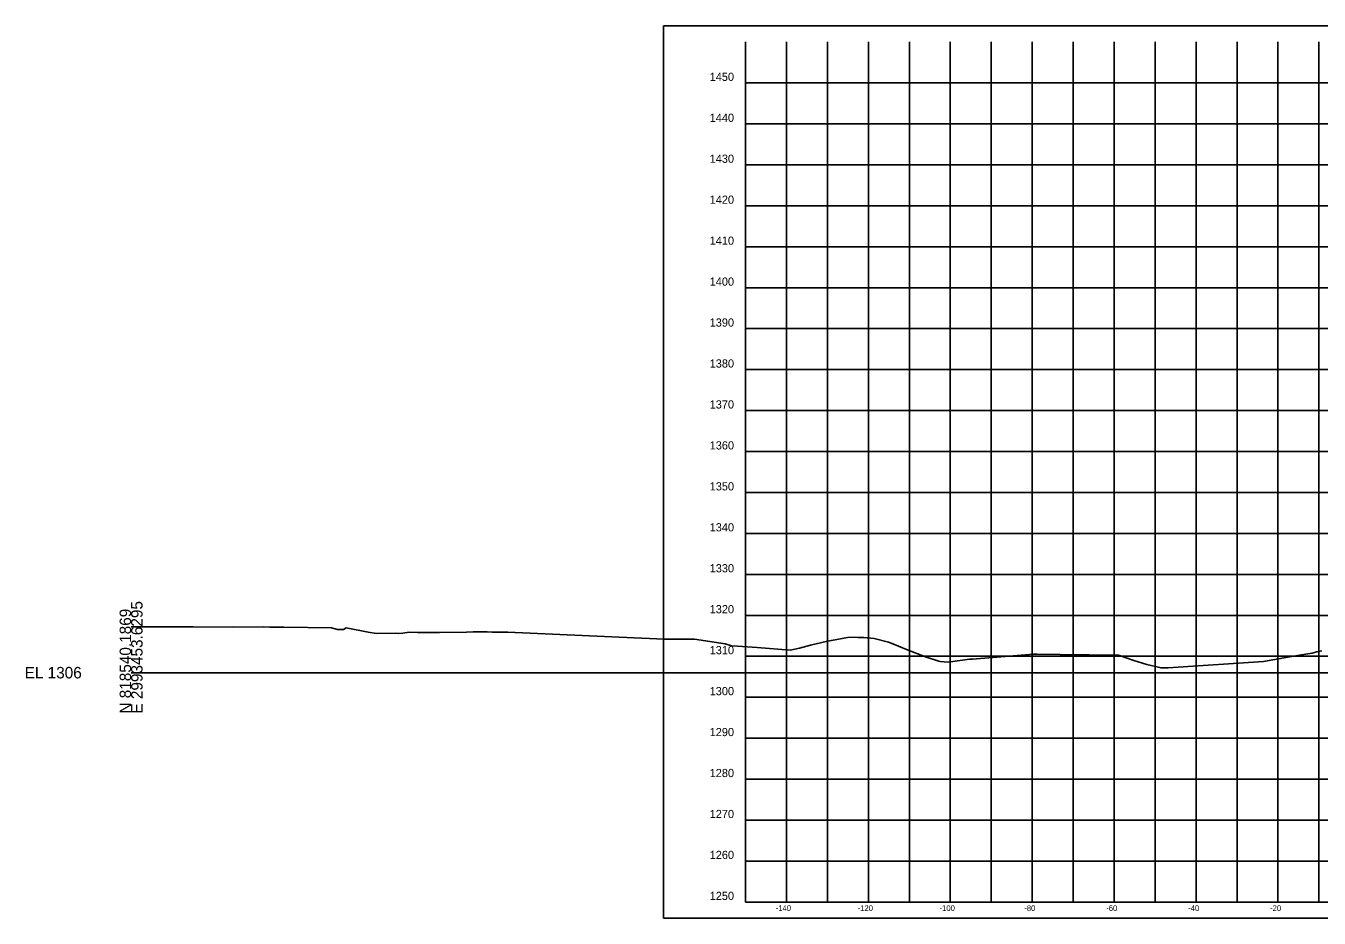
# Model space of a CAD drawing. Extents: x -26 to 603, y -60 to 663.
# Drawn here: x -25.7 to 290, y -59.9 to 157.9 of the extents above; entities that cross this region are included whole.
import ezdxf

# ---------------------------------------------------------------- set-up
doc = ezdxf.new("R2010")
doc.units = 0
for name, color, linetype in [('DESIGN - SHEET - Corner Text', 7, 'Continuous'), ('DESIGN - SHEET - Light Grid', 7, 'Continuous'), ('DESIGN - SHEET - Linework', 7, 'Continuous'), ('DESIGN - SHEET - Plot Shape', 7, 'Continuous'), ('SURVEY - GROUND - Top of Ground', 7, 'Continuous')]:
    doc.layers.add(name, color=color, linetype=linetype)

msp = doc.modelspace()

# ---------------------------------------------------------------- linework, layer by layer
at = {"layer": 'DESIGN - SHEET - Light Grid'}
msp.add_line((0, 0), (300, 0), dxfattribs=at)
at = {"layer": 'DESIGN - SHEET - Linework'}
for p, q in [((160, -56), (160, 154)), ((170, -56), (170, 154)), ((180, -56), (180, 154)), ((190, -56), (190, 154)), ((200, -56), (200, 154)), ((210, -56), (210, 154)), ((220, -56), (220, 154)), ((230, -56), (230, 154)), ((240, -56), (240, 154)), ((250, -56), (250, 154)), ((260, -56), (260, 154)), ((270, -56), (270, 154)), ((280, -56), (280, 154)), ((290, -56), (290, 154)), ((150, 144), (450, 144)), ((150, 134), (450, 134)), ((150, 124), (450, 124)), ((150, 114), (450, 114)), ((150, 104), (450, 104)), ((150, 94), (450, 94)), ((150, 84), (450, 84)), ((150, 74), (450, 74)), ((150, 64), (450, 64)), ((150, 54), (450, 54)), ((150, 44), (450, 44)), ((150, 34), (450, 34)), ((150, 24), (450, 24)), ((150, 14), (450, 14)), ((150, 4), (450, 4)), ((150, -6), (450, -6)), ((150, -16), (450, -16)), ((150, -26), (450, -26)), ((150, -36), (450, -36)), ((150, -46), (450, -46))]:
    msp.add_line(p, q, dxfattribs=at)
msp.add_lwpolyline([(150, 154), (150, -56), (450, -56), (450, 154)], dxfattribs=at)
at = {"layer": 'DESIGN - SHEET - Plot Shape'}
msp.add_lwpolyline([(130, 157.94), (470, 157.94), (470, -59.94), (130, -59.94)], close=True, dxfattribs=at)
at = {"layer": 'SURVEY - GROUND - Top of Ground'}
msp.add_lwpolyline([(0, 11.19), (2.71, 11.19), (7.57, 11.19), (15.18, 11.18), (25.08, 11.15), (32.21, 11.16), (33.83, 11.15), (34.58, 11.15), (37.3, 11.12), (48.91, 10.97), (50.41, 10.56), (50.88, 10.55), (51.86, 10.55), (52.5, 10.95), (57.9, 9.86), (59.93, 9.58), (64.55, 9.64), (65.39, 9.55), (66.34, 9.66), (67.89, 9.88), (69.96, 9.83), (75.32, 9.77), (81.88, 9.92), (83.47, 9.94), (86.91, 9.95), (88.12, 9.91), (91.98, 9.86), (97.45, 9.61), (122.79, 8.53), (130.23, 8.22), (137.58, 8.21), (145.03, 7.02), (146.55, 6.58), (148.05, 6.47), (152.81, 6.17), (160.87, 5.53), (163.17, 5.95), (165.86, 6.7), (170, 7.66), (170.97, 7.88), (174.93, 8.6), (176.47, 8.64), (177.53, 8.62), (177.95, 8.62), (178.87, 8.61), (181.38, 8.33), (184.93, 7.48), (186.37, 6.85), (189.28, 5.63), (193.96, 3.83), (197.2, 2.8), (197.55, 2.75), (199.48, 2.59), (200.05, 2.66), (204.69, 3.32), (205.42, 3.32), (220.33, 4.53), (221.1, 4.55), (226.85, 4.42), (241.02, 4.26), (244.83, 2.99), (247.99, 2.02), (251.47, 1.18), (253.19, 1.16), (276.5, 2.74), (282.4, 3.76), (283.84, 4.05), (285.26, 4.29), (288.37, 4.8), (289.45, 5.06), (290.7, 5.32)], dxfattribs=at)

# ---------------------------------------------------------------- texts
at = {"layer": 'DESIGN - SHEET - Corner Text'}
for s, height, p in [('1450', 2, (141.25, 144.5)), ('1440', 2, (141.25, 134.5)), ('1430', 2, (141.25, 124.5)), ('1420', 2, (141.25, 114.5)), ('1410', 2, (141.25, 104.5)), ('1400', 2, (141.25, 94.5)), ('1390', 2, (141.25, 84.5)), ('1380', 2, (141.25, 74.5)), ('1370', 2, (141.25, 64.5)), ('1360', 2, (141.25, 54.5)), ('1350', 2, (141.25, 44.5)), ('1340', 2, (141.25, 34.5)), ('1330', 2, (141.25, 24.5)), ('1320', 2, (141.25, 14.5)), ('1310', 2, (141.25, 4.5)), ('1300', 2, (141.25, -5.5)), ('1290', 2, (141.25, -15.5)), ('1280', 2, (141.25, -25.5)), ('1270', 2, (141.25, -35.5)), ('1260', 2, (141.25, -45.5)), ('1250', 2, (141.25, -55.5)), ('-140', 1.4, (157.37, -58.2)), ('-120', 1.4, (177.37, -58.2)), ('-100', 1.4, (197.37, -58.2)), ('-80', 1.4, (218.06, -58.2)), ('-60', 1.4, (238.06, -58.2)), ('-40', 1.4, (258.06, -58.2)), ('-20', 1.4, (278.06, -58.2))]:
    msp.add_text(s, height=height, dxfattribs=at).set_placement(p)
at = {"layer": 'DESIGN - SHEET - Light Grid'}
for s, p in [('E 2993453.6295', (2.8, -10)), ('N 818540.1869', (0, -10))]:
    msp.add_text(s, height=2.8, rotation=90, dxfattribs=at).set_placement(p)
msp.add_text('EL 1306', height=2.8, dxfattribs=at).set_placement((-26, -1.4))

doc.saveas('drawing.dxf')
